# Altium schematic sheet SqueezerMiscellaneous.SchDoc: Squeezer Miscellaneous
size C; Organization: LIGO Laboratory; Address1: California Institute of Technology; Address2: Massachusetts Institute of Technology; SheetNumber: 37; SheetTotal: 39; DrawnBy: R.  Abbott; Engineer: R.  Abbott; PageSetup: Record=PageOptions¦CenterHorizontal=True¦CenterVertical=True¦PrintScale=1.09¦XCorrection=1.00¦YCorrection=1.00¦PrintKind=0¦BorderSize=5000000¦LeftOffset=0¦BottomOffset=0¦Orientation=2¦PaperLength=1000¦PaperWidth=1000¦Scale=100¦PaperSource=7¦PrintQuality=-4¦MediaType=1¦DitherType=10¦PaperKind=11x17¦PrintScaleMode=1
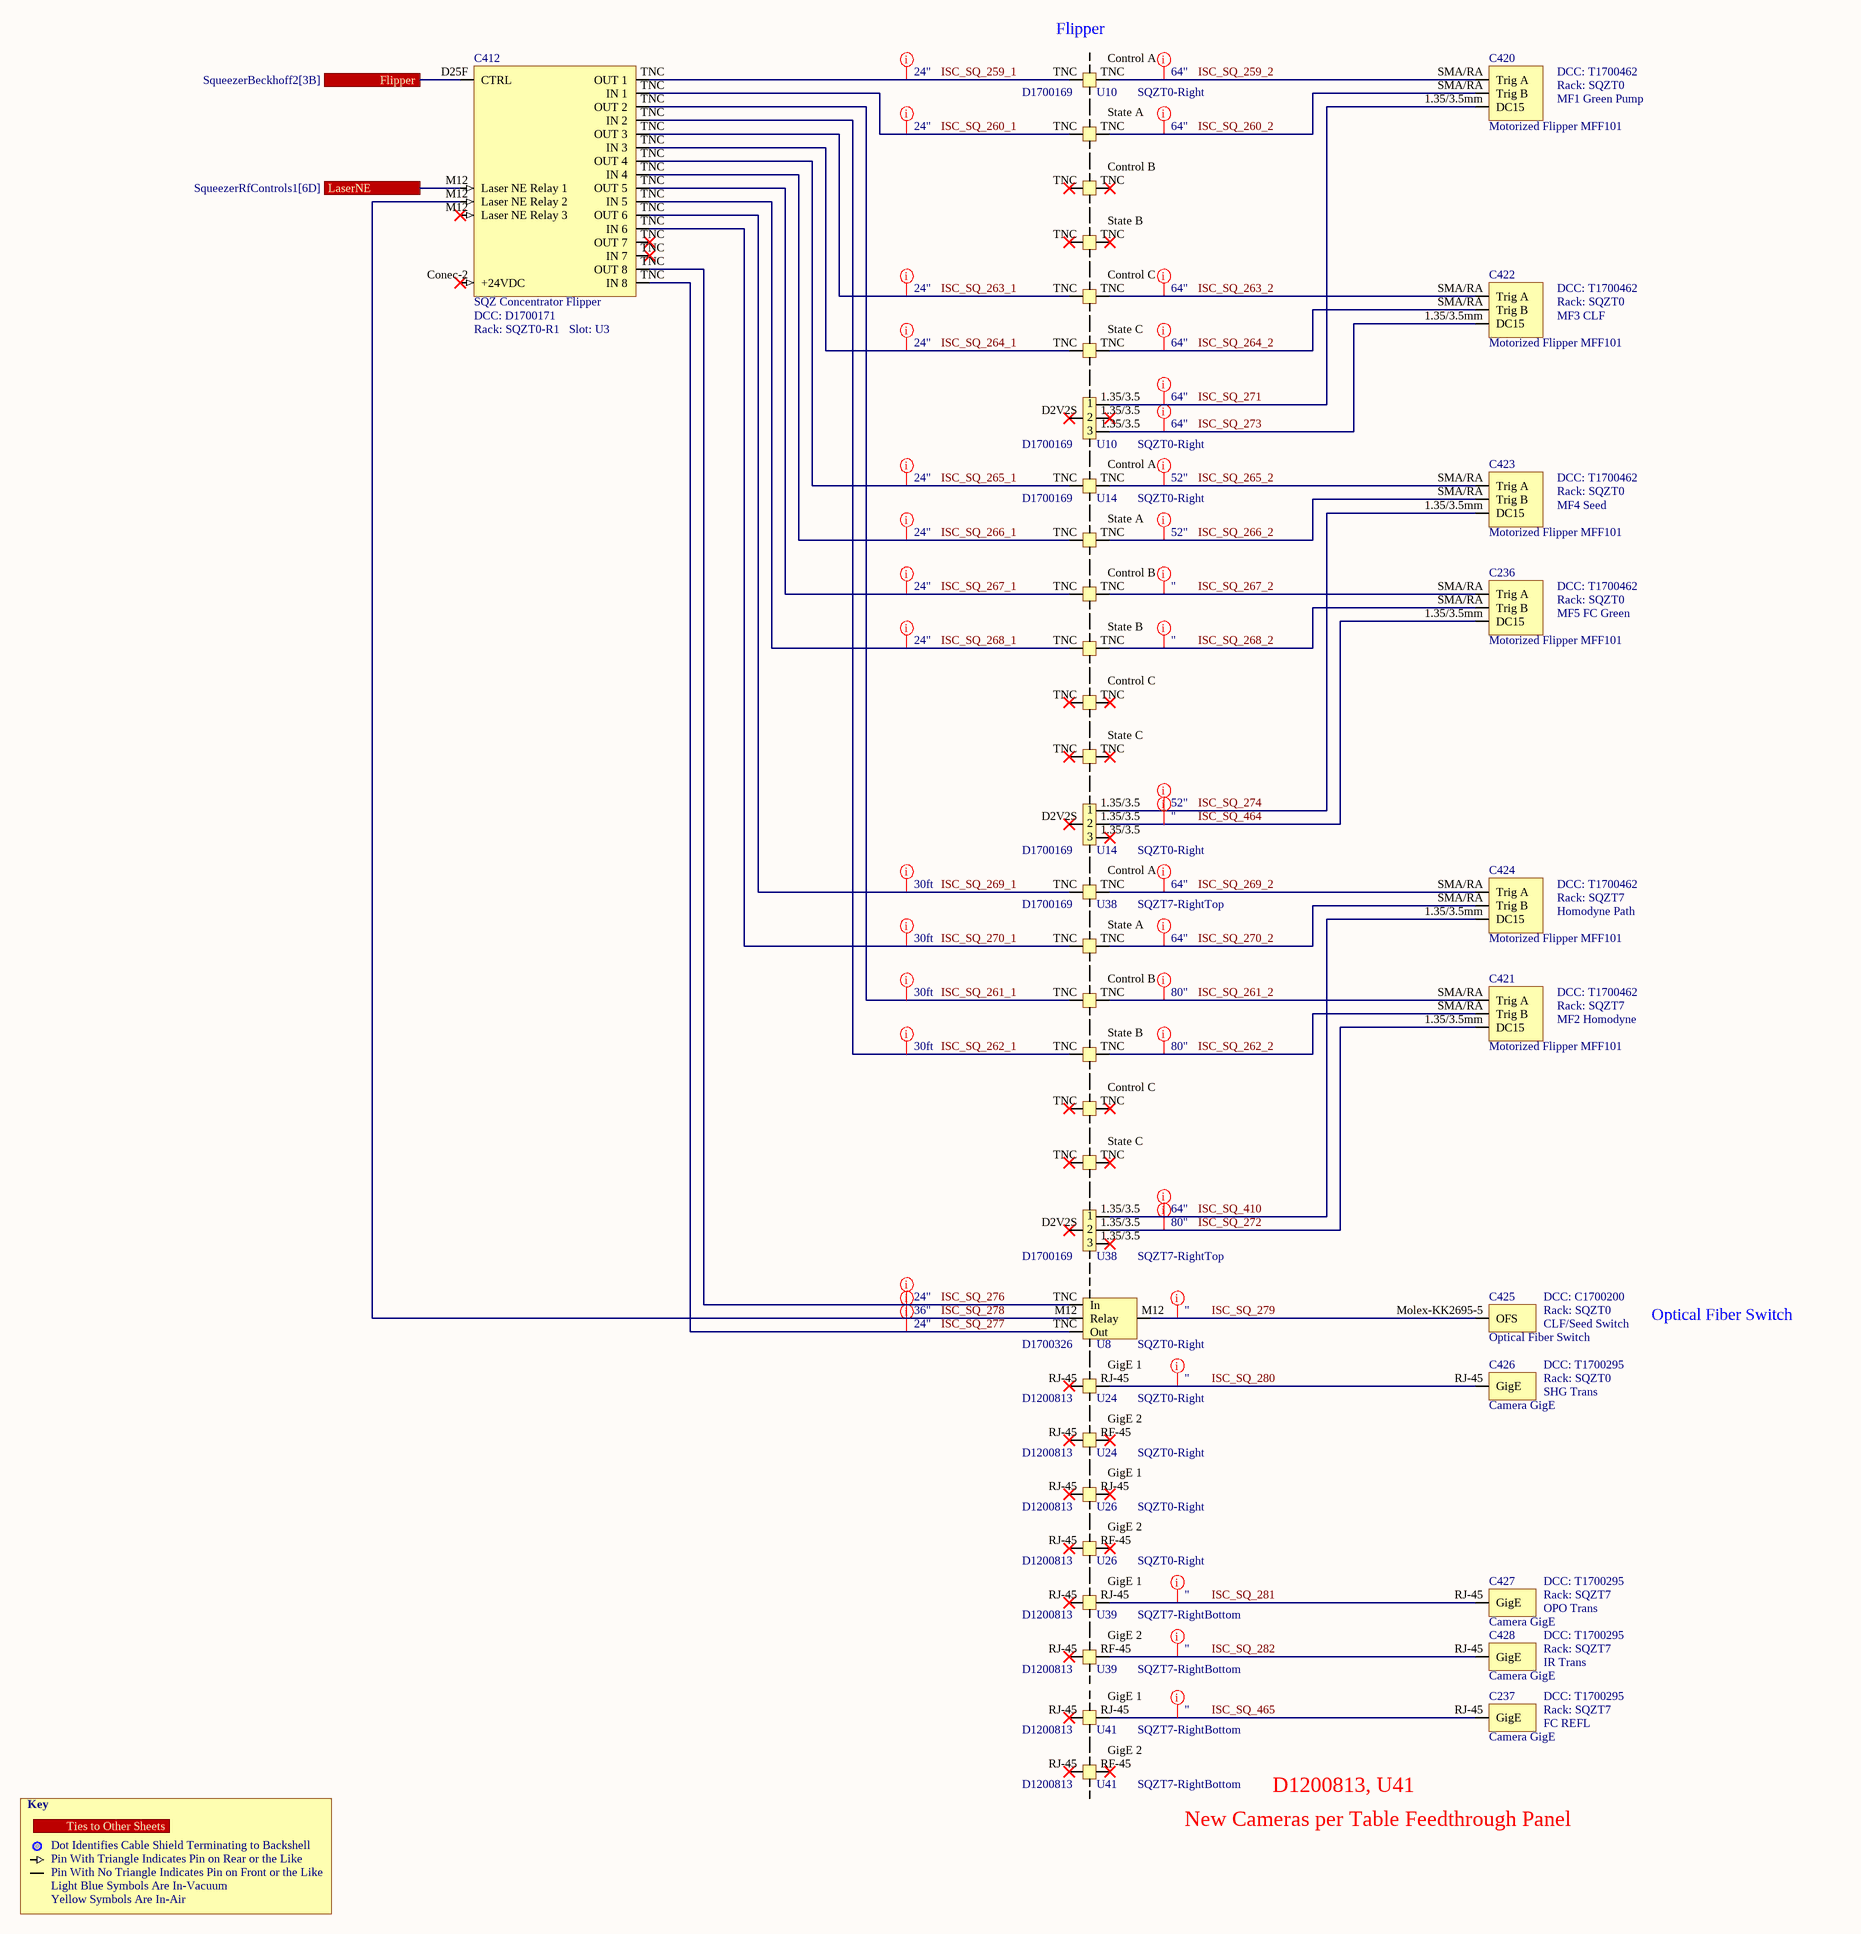
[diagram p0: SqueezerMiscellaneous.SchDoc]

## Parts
C228  DCC: D1200813  Rack: SQZT7-RightBottom  Slot: U41  (hidden comment: Patch Panel GigE Camera)  (parts A,B of 2)
C236  Motorized Flipper MFF101  DCC: T1700462  Rack: SQZT0  Slot: MF5 FC Green
C237  Camera GigE  DCC: T1700295  Rack: SQZT7  Slot: FC REFL
C412  SQZ Concentrator Flipper  DCC: D1700171  Rack: SQZT0-R1  Slot: U3
C413  DCC: D1700169  Rack: SQZT0-Right  Slot: U10  (hidden comment: Patch Panel Motorized Flipper)  (parts A,B,C,D,E,F,G of 7)
C414  DCC: D1700169  Rack: SQZT0-Right  Slot: U14  (hidden comment: Patch Panel Motorized Flipper)  (parts A,B,C,D,E,F,G of 7)
C415  DCC: D1700169  Rack: SQZT7-RightTop  Slot: U38  (hidden comment: Patch Panel Motorized Flipper)  (parts A,B,C,D,E,F,G of 7)
C416  DCC: D1700326  Rack: SQZT0-Right  Slot: U8  (hidden comment: Patch Panel Optical Fiber Switch)
C417  DCC: D1200813  Rack: SQZT0-Right  Slot: U24  (hidden comment: Patch Panel GigE Camera)  (parts A,B of 2)
C418  DCC: D1200813  Rack: SQZT0-Right  Slot: U26  (hidden comment: Patch Panel GigE Camera)  (parts A,B of 2)
C419  DCC: D1200813  Rack: SQZT7-RightBottom  Slot: U39  (hidden comment: Patch Panel GigE Camera)  (parts A,B of 2)
C420  Motorized Flipper MFF101  DCC: T1700462  Rack: SQZT0  Slot: MF1 Green Pump
C421  Motorized Flipper MFF101  DCC: T1700462  Rack: SQZT7  Slot: MF2 Homodyne
C422  Motorized Flipper MFF101  DCC: T1700462  Rack: SQZT0  Slot: MF3 CLF
C423  Motorized Flipper MFF101  DCC: T1700462  Rack: SQZT0  Slot: MF4 Seed
C424  Motorized Flipper MFF101  DCC: T1700462  Rack: SQZT7  Slot: Homodyne Path
C425  Optical Fiber Switch  DCC: C1700200  Rack: SQZT0  Slot: CLF/Seed Switch
C426  Camera GigE  DCC: T1700295  Rack: SQZT0  Slot: SHG Trans
C427  Camera GigE  DCC: T1700295  Rack: SQZT7  Slot: OPO Trans
C428  Camera GigE  DCC: T1700295  Rack: SQZT7  Slot: IR Trans

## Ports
Flipper (see SqueezerBeckhoff2[3B]), LaserNE (see SqueezerRfControls1[6D]), Ties to Other Sheets

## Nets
Flipper: C412.D25F(CTRL) ; port Flipper
ISC_SQ_259_1: C412.TNC(OUT_1) C413.TNC(ControlA)
ISC_SQ_259_2: C413.TNC(ControlA) C420.SMA/RA(Trig_A)
ISC_SQ_260_1: C412.TNC(IN_1) C413.TNC(StateA)
ISC_SQ_260_2: C413.TNC(StateA) C420.SMA/RA(Trig_B)
ISC_SQ_261_1: C412.TNC(OUT_2) C415.TNC(ControlB)
ISC_SQ_261_2: C415.TNC(ControlB) C421.SMA/RA(Trig_A)
ISC_SQ_262_1: C412.TNC(IN_2) C415.TNC(StateB)
ISC_SQ_262_2: C415.TNC(StateB) C421.SMA/RA(Trig_B)
ISC_SQ_263_1: C412.TNC(OUT_3) C413.TNC(ControlC)
ISC_SQ_263_2: C413.TNC(ControlC) C422.SMA/RA(Trig_A)
ISC_SQ_264_1: C412.TNC(IN_3) C413.TNC(StateC)
ISC_SQ_264_2: C413.TNC(StateC) C422.SMA/RA(Trig_B)
ISC_SQ_265_1: C412.TNC(OUT_4) C414.TNC(ControlA)
ISC_SQ_265_2: C414.TNC(ControlA) C423.SMA/RA(Trig_A)
ISC_SQ_266_1: C412.TNC(IN_4) C414.TNC(StateA)
ISC_SQ_266_2: C414.TNC(StateA) C423.SMA/RA(Trig_B)
ISC_SQ_267_1: C412.TNC(OUT_5) C414.TNC(ControlB)
ISC_SQ_267_2: C236.SMA/RA(Trig_A) C414.TNC(ControlB)
ISC_SQ_268_1: C412.TNC(IN_5) C414.TNC(StateB)
ISC_SQ_268_2: C236.SMA/RA(Trig_B) C414.TNC(StateB)
ISC_SQ_269_1: C412.TNC(OUT_6) C415.TNC(ControlA)
ISC_SQ_269_2: C415.TNC(ControlA) C424.SMA/RA(Trig_A)
ISC_SQ_270_1: C412.TNC(IN_6) C415.TNC(StateA)
ISC_SQ_270_2: C415.TNC(StateA) C424.SMA/RA(Trig_B)
ISC_SQ_271: C413.1.35/3.5(Barrel2) C420.1.35/3.5mm(DC15)
ISC_SQ_272: C415.1.35/3.5(Barrel2) C421.1.35/3.5mm(DC15)
ISC_SQ_273: C413.1.35/3.5(Barrel3) C422.1.35/3.5mm(DC15)
ISC_SQ_274: C414.1.35/3.5(Barrel1) C423.1.35/3.5mm(DC15)
ISC_SQ_276: C412.TNC(OUT_8) C416.TNC(In)
ISC_SQ_277: C412.TNC(IN_8) C416.TNC(Out)
ISC_SQ_278: C412.M12(Laser_NE_Relay_2) C416.M12(Relay)
ISC_SQ_279: C416.M12(Switch) C425.Molex-KK2695-5(OFS)
ISC_SQ_280: C417.RJ-45 C426.RJ-45(GigE)
ISC_SQ_281: C419.RJ-45 C427.RJ-45(GigE)
ISC_SQ_282: C419.RF-45 C428.RJ-45(GigE)
ISC_SQ_410: C415.1.35/3.5(Barrel1) C424.1.35/3.5mm(DC15)
ISC_SQ_464: C236.1.35/3.5mm(DC15) C414.1.35/3.5(Barrel2)
ISC_SQ_465: C228.RJ-45 C237.RJ-45(GigE)
LaserNE: C412.M12(Laser_NE_Relay_1) ; port LaserNE

Not connected (* = marked no-connect by the designer): C228 RF-45(2)*; C412 Conec-2(+24VDC)*; C413 D2V2S(Power)*; C414 D2V2S(Power)*; C415 D2V2S(Power)*; C417 RF-45(2)*; C418 RF-45(2)* RJ-45(1)*

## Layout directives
Length: 24": ISC_SQ_259_1, ISC_SQ_260_1, ISC_SQ_263_1, ISC_SQ_264_1, ISC_SQ_265_1, ISC_SQ_266_1, ISC_SQ_267_1, ISC_SQ_268_1, ISC_SQ_276, ISC_SQ_277
Length: 30ft: ISC_SQ_261_1, ISC_SQ_262_1, ISC_SQ_269_1, ISC_SQ_270_1
Length: 64": ISC_SQ_259_2, ISC_SQ_260_2, ISC_SQ_263_2, ISC_SQ_264_2, ISC_SQ_269_2, ISC_SQ_270_2, ISC_SQ_271, ISC_SQ_273, ISC_SQ_410
Length: 80": ISC_SQ_261_2, ISC_SQ_262_2, ISC_SQ_272
Length: 52": ISC_SQ_265_2, ISC_SQ_266_2, ISC_SQ_274
Length: 36": ISC_SQ_278
Length: ": ISC_SQ_267_2, ISC_SQ_268_2, ISC_SQ_279, ISC_SQ_280, ISC_SQ_281, ISC_SQ_282, ISC_SQ_464, ISC_SQ_465

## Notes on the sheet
- (near C413) Flipper
- Optical Fiber Switch
- Key
- Dot Identifies Cable Shield Terminating to Backshell
- New Cameras per Table Feedthrough Panel
- D1200813, U41
- Pin With Triangle Indicates Pin on Rear or the Like
- Pin With No Triangle Indicates Pin on Front or the Like
- Light Blue Symbols Are In-Vacuum
- Yellow Symbols Are In-Air

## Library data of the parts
C228 C417-C419 = Patch Panel GigE Camera: Patch Panel (D1200813); Serial: Sxxxxxxx; System: ISC
C236 C420-C424 = Motorized Flipper: Serial: Sxxxxxxx; System: ISC
C237 C426-C428 = Camera GigE: Serial: Sxxxxxxx; System: ISC
C412 = SQZ Concentrator Flipper: Serial: Sxxxxxxx; System: ISC
C413-C415 = Patch Panel Motorized Flipper: Patch Panel (D1700169); Serial: Sxxxxxxx; System: ISC
C416 = Patch Panel Optical Fiber Switch: Patch Panel (D1700326); Serial: Sxxxxxxx; System: ISC
C425 = Optical Fiber Switch: Optical Fiber Switch Thorlabs OSW12-980-SM; Serial: Sxxxxxxx; System: ISC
